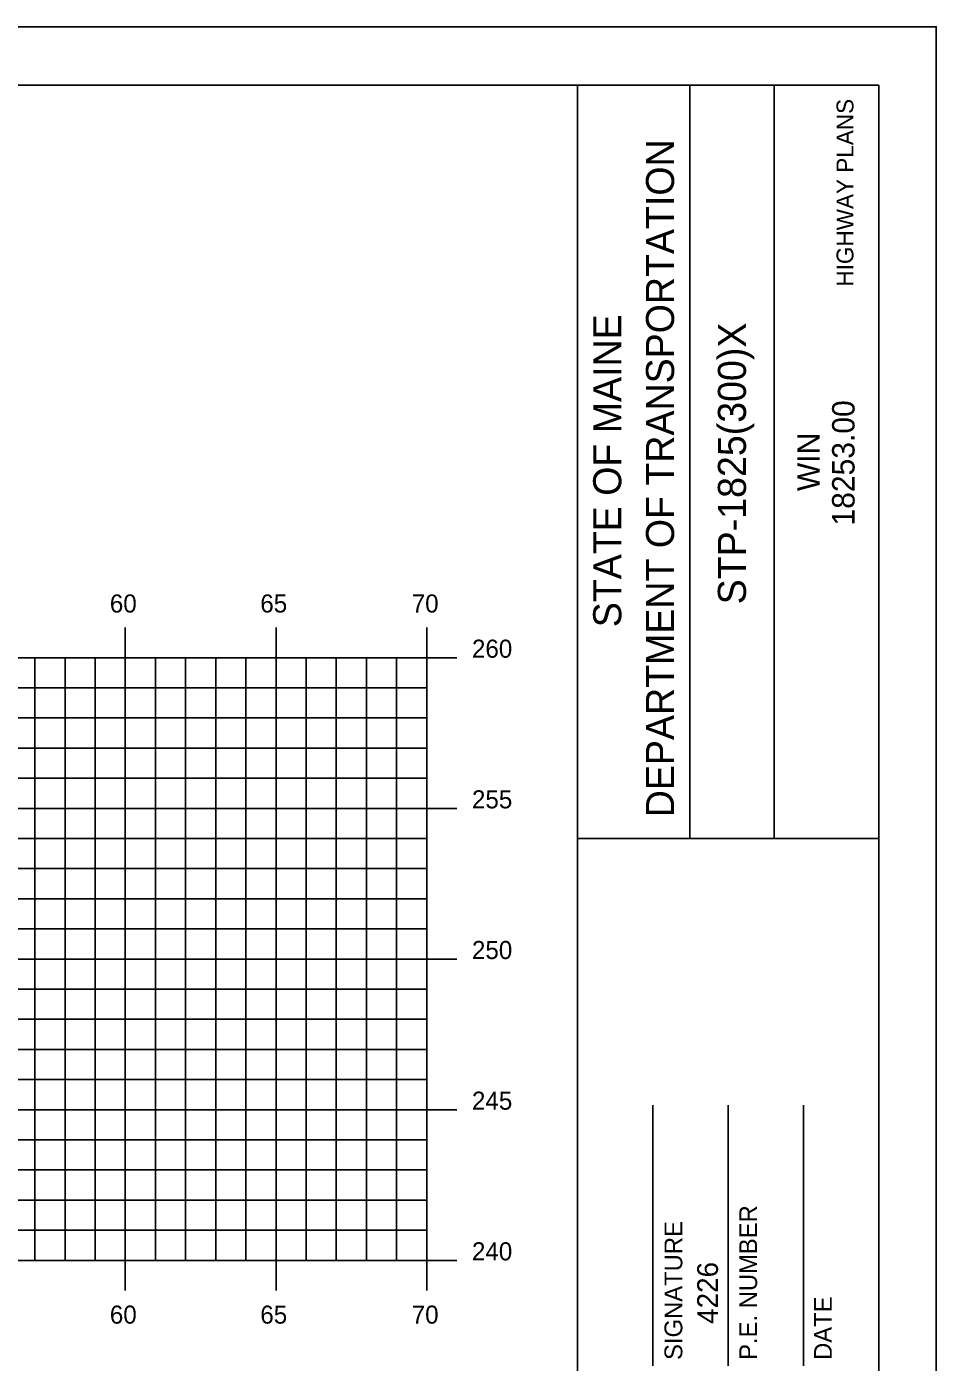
# Model space of a CAD drawing. Extents: x 859129 to 859299, y 366268 to 366378.
# Drawn here: x 859269.19 to 859299.37, y 366333.85 to 366378.18 of the extents above; entities that cross this region are included whole.
import ezdxf

# ---------------------------------------------------------------- set-up
doc = ezdxf.new("R2010")
doc.units = 0
for name, color, linetype in [('ANNOTATION', 7, 'Continuous'), ('BORDER', 7, 'Continuous'), ('H_V ANNOTATION', 7, 'Continuous'), ('HIGHWAY_TITLE', 7, 'Continuous'), ('MAJOR', 7, 'Continuous'), ('MINOR', 7, 'Continuous'), ('PLOT BOUNDARY', 7, 'Continuous')]:
    doc.layers.add(name, color=color, linetype=linetype)

msp = doc.modelspace()

# ---------------------------------------------------------------- linework, layer by layer
at = {"layer": 'BORDER'}
for p, q in [((859297.462, 366376.236), (859137.462, 366376.236)), ((859287.462, 366271.236), (859287.462, 366376.239)), ((859291.19, 366351.234), (859291.19, 366376.234)), ((859293.985, 366351.234), (859293.985, 366376.234)), ((859297.462, 366271.236), (859297.462, 366376.236)), ((859287.463, 366351.231), (859297.462, 366351.231)), ((859289.962, 366333.739), (859289.962, 366342.387)), ((859292.462, 366333.739), (859292.462, 366342.387)), ((859294.962, 366333.739), (859294.962, 366342.387))]:
    msp.add_line(p, q, dxfattribs=at)
at = {"layer": 'MAJOR'}
for p, q in [((859272.462, 366358.238), (859272.462, 366357.236)), ((859277.462, 366358.238), (859277.462, 366357.236)), ((859282.462, 366358.238), (859282.462, 366357.236)), ((859142.462, 366357.236), (859282.462, 366357.236)), ((859142.462, 366357.236), (859282.462, 366357.236)), ((859272.462, 366337.236), (859272.462, 366357.236)), ((859277.462, 366337.236), (859277.462, 366357.236)), ((859283.464, 366357.236), (859281.46, 366357.236)), ((859282.462, 366337.236), (859282.462, 366357.236)), ((859282.462, 366337.236), (859282.462, 366357.236)), ((859142.462, 366352.236), (859282.462, 366352.236)), ((859283.464, 366352.236), (859281.46, 366352.236)), ((859142.462, 366347.236), (859282.462, 366347.236)), ((859283.464, 366347.236), (859281.46, 366347.236)), ((859142.462, 366342.236), (859282.462, 366342.236)), ((859283.464, 366342.236), (859281.46, 366342.236)), ((859142.462, 366337.236), (859282.462, 366337.236)), ((859142.462, 366337.236), (859282.462, 366337.236)), ((859272.462, 366336.234), (859272.462, 366337.236)), ((859277.462, 366336.234), (859277.462, 366337.236)), ((859283.464, 366337.236), (859281.46, 366337.236)), ((859282.462, 366336.234), (859282.462, 366337.236))]:
    msp.add_line(p, q, dxfattribs=at)
at = {"layer": 'MINOR'}
for p, q in [((859269.462, 366337.236), (859269.462, 366357.236)), ((859270.462, 366337.236), (859270.462, 366357.236)), ((859271.462, 366337.236), (859271.462, 366357.236)), ((859273.462, 366337.236), (859273.462, 366357.236)), ((859274.462, 366337.236), (859274.462, 366357.236)), ((859275.462, 366337.236), (859275.462, 366357.236)), ((859276.462, 366337.236), (859276.462, 366357.236)), ((859278.462, 366337.236), (859278.462, 366357.236)), ((859279.462, 366337.236), (859279.462, 366357.236)), ((859280.462, 366337.236), (859280.462, 366357.236)), ((859281.462, 366337.236), (859281.462, 366357.236)), ((859142.462, 366356.236), (859282.462, 366356.236)), ((859282.462, 366356.236), (859281.46, 366356.236)), ((859142.462, 366355.236), (859282.462, 366355.236)), ((859282.462, 366355.236), (859281.46, 366355.236)), ((859142.462, 366354.236), (859282.462, 366354.236)), ((859282.462, 366354.236), (859281.46, 366354.236)), ((859142.462, 366353.236), (859282.462, 366353.236)), ((859282.462, 366353.236), (859281.46, 366353.236)), ((859142.462, 366351.236), (859282.462, 366351.236)), ((859282.462, 366351.236), (859281.46, 366351.236)), ((859142.462, 366350.236), (859282.462, 366350.236)), ((859282.462, 366350.236), (859281.46, 366350.236)), ((859142.462, 366349.236), (859282.462, 366349.236)), ((859282.462, 366349.236), (859281.46, 366349.236)), ((859142.462, 366348.236), (859282.462, 366348.236)), ((859282.462, 366348.236), (859281.46, 366348.236)), ((859142.462, 366346.236), (859282.462, 366346.236)), ((859282.462, 366346.236), (859281.46, 366346.236)), ((859142.462, 366345.236), (859282.462, 366345.236)), ((859282.462, 366345.236), (859281.46, 366345.236)), ((859142.462, 366344.236), (859282.462, 366344.236)), ((859282.462, 366344.236), (859281.46, 366344.236)), ((859142.462, 366343.236), (859282.462, 366343.236)), ((859282.462, 366343.236), (859281.46, 366343.236)), ((859142.462, 366341.236), (859282.462, 366341.236)), ((859282.462, 366341.236), (859281.46, 366341.236)), ((859142.462, 366340.236), (859282.462, 366340.236)), ((859282.462, 366340.236), (859281.46, 366340.236)), ((859142.462, 366339.236), (859282.462, 366339.236)), ((859282.462, 366339.236), (859281.46, 366339.236)), ((859142.462, 366338.236), (859282.462, 366338.236)), ((859282.462, 366338.236), (859281.46, 366338.236))]:
    msp.add_line(p, q, dxfattribs=at)
at = {"layer": 'PLOT BOUNDARY'}
msp.add_lwpolyline([(859129.368, 366268.177), (859299.368, 366268.177), (859299.368, 366378.177), (859129.368, 366378.177)], close=True, dxfattribs=at)

# ---------------------------------------------------------------- texts
at = {"layer": 'ANNOTATION'}
msp.add_text('4226', height=0.69, rotation=90, dxfattribs=at).set_placement((859292.126, 366335.13))
at = {"layer": 'BORDER'}
for s, height, p in [('DEPARTMENT OF TRANSPORTATION', 0.93176, (859290.669, 366351.942)), ('STATE OF MAINE', 0.93176, (859288.917, 366358.248)), ('STP-1825(300)X', 0.93176, (859293.054, 366359.008)), ('18253.00', 0.7453, (859296.657, 366361.623)), ('WIN', 0.7453, (859295.499, 366362.766)), ('P.E. NUMBER', 0.59055, (859293.423, 366333.932)), ('SIGNATURE', 0.5906, (859290.942, 366333.932)), ('DATE', 0.5906, (859295.903, 366333.932))]:
    msp.add_text(s, height=height, rotation=90, dxfattribs=at).set_placement(p)
at = {"layer": 'H_V ANNOTATION'}
for s, p in [('60', (859271.948, 366358.736)), ('65', (859276.94, 366358.736)), ('70', (859281.964, 366358.736)), ('260', (859283.962, 366357.236)), ('255', (859283.962, 366352.236)), ('250', (859283.962, 366347.236)), ('245', (859283.962, 366342.236)), ('240', (859283.962, 366337.236)), ('60', (859271.948, 366335.136)), ('65', (859276.94, 366335.136)), ('70', (859281.964, 366335.136))]:
    msp.add_text(s, height=0.6, dxfattribs=at).set_placement(p)
at = {"layer": 'HIGHWAY_TITLE'}
msp.add_text('HIGHWAY PLANS', height=0.55901, rotation=90, dxfattribs=at).set_placement((859296.62, 366369.552))

doc.saveas('drawing.dxf')
